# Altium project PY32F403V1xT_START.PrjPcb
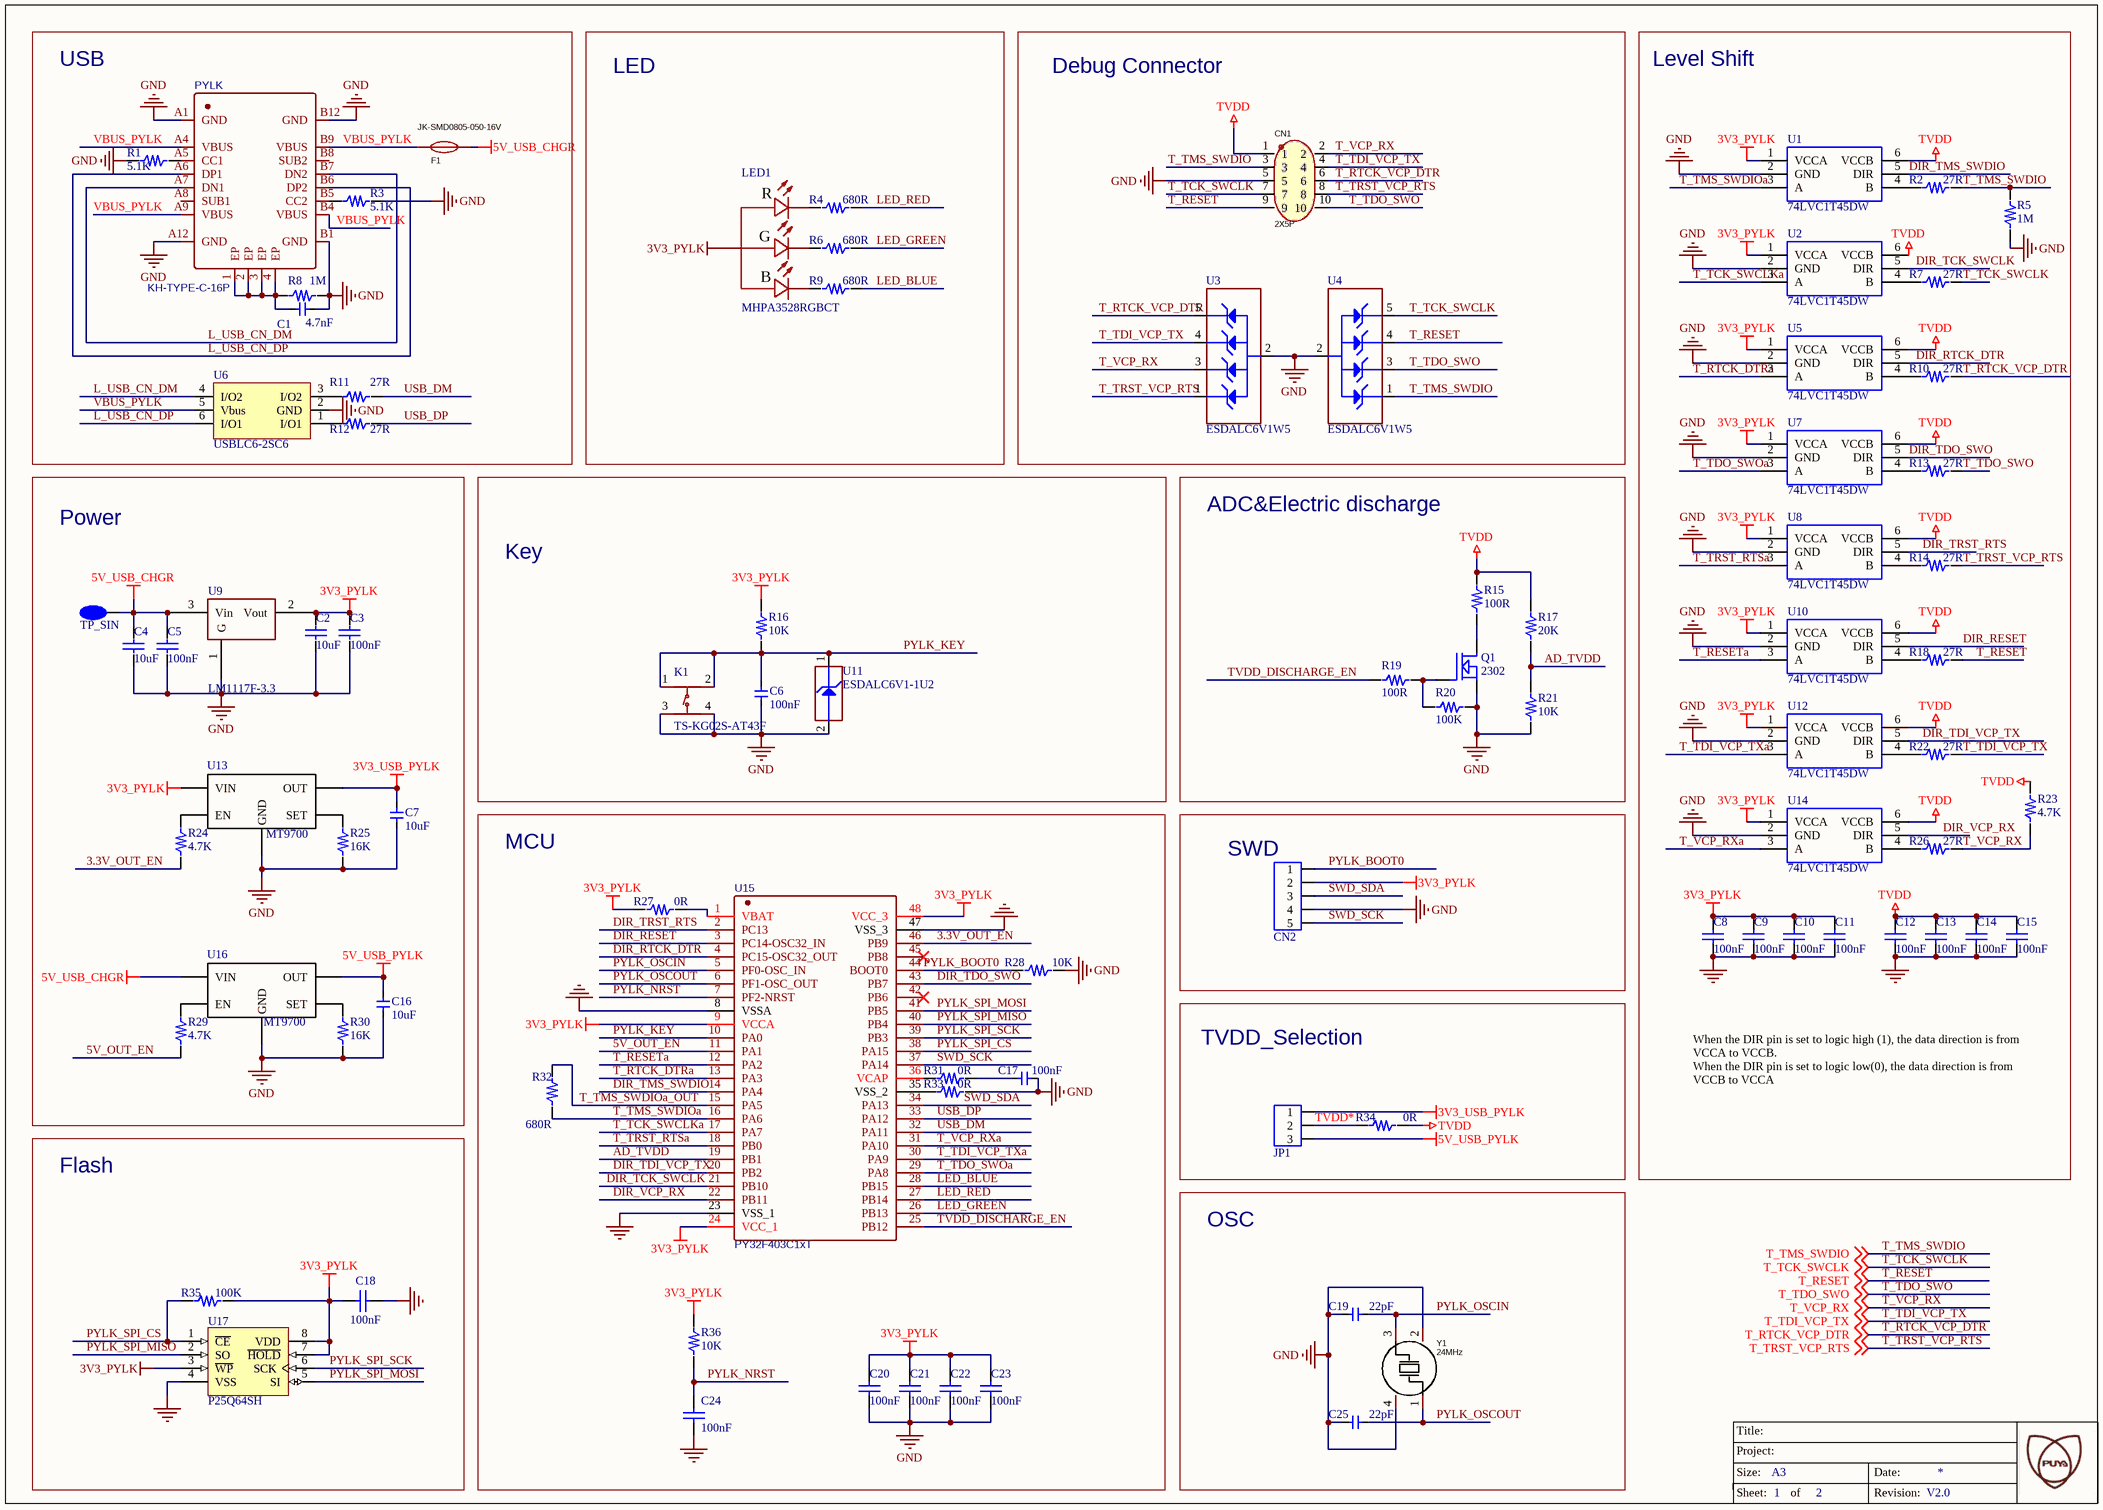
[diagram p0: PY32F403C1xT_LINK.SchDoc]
2 sheets, 171 parts. Net scope: global (net labels, ports and power ports of the same name join across sheets).
Board file: PY32F403V1xT_START.PcbDoc
Sheets:
  PY32F403C1xT_LINK.SchDoc
  PY32F403V1xT_START.SchDoc

## Sheet PY32F403C1xT_LINK.SchDoc: =DocumentName
size A3; Revision: V2.0; SheetNumber: 1; SheetTotal: 2; Project: PY32F403V1xT_START.PrjPcb

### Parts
5V_USB_CHGR  TP_SIN  [TP_SIN]
C1  4.7nF  [C0603]
C2  10uF  [C0805]
C3  100nF  [C0603]
C4  10uF  [C0805]
C5  100nF  [C0603]
C6  100nF  [C0603]
C7  10uF  [C0805]
C8  100nF  [C0603]
C9  100nF  [C0603]
C10  100nF  [C0603]
C11  100nF  [C0603]
C12  100nF  [C0603]
C13  100nF  [C0603]
C14  100nF  [C0603]
C15  100nF  [C0603]
C16  10uF  [C0805]
C17  100nF  [C0603]
C18  100nF  [C0603]
C19  22pF  [C0603]
C20  100nF  [C0603]
C21  100nF  [C0603]
C22  100nF  [C0603]
C23  100nF  [C0603]
C24  100nF  [C0603]
C25  22pF  [C0603]
CN1  2X5P  [HDR2X5]
CN2  CON5  [CON5]  (value not drawn)
F1  JK-SMD0805-050-16V  [F0805]
JP1  CON3  [CON3]  (value not drawn)
K1  TS-KG02S-AT43F  [SW-SMD_4P-L6.0-W6.0-P4.50-LS8.5]
LED1  MHPA3528RGBCT  [LED-ARRAY-SMD_4P-L3.5-W2.8-TL]
PYLK  KH-TYPE-C-16P  [USB-C-SMD_KH-TYPE-C-16P]
Q1  2302  [SOT23]
R1  5.1K  [R0603]
R2  27R  [R0603]
R3  5.1K  [R0603]
R4  680R  [R0603]
R5  1M  [R0603]
R6  680R  [R0603]
R7  27R  [R0603]
R8  1M  [R0603]
R9  680R  [R0603]
R10  27R  [R0603]
R11  27R  [R0603]
R12  27R  [R0603]
R13  27R  [R0603]
R14  27R  [R0603]
R15  100R  [R0805]
R16  10K  [R0603]
R17  20K  [R0603]
R18  27R  [R0603]
R19  100R  [R0603]
R20  100K  [R0603]
R21  10K  [R0603]
R22  27R  [R0603]
R23  4.7K  [R0603]
R24  4.7K  [R0603]
R25  16K  [R0603]
R26  27R  [R0603]
R27  0R  [JP2_SMD]
R28  10K  [R0603]
R29  4.7K  [R0603]
R30  16K  [R0603]
R31  0R  [JP2_SMD]
R32  680R  [R0603]
R33  0R  [JP2_SMD]
R34  0R  [JP2_SMD]
R35  100K  [R0603]
R36  10K  [R0603]
U1  74LVC1T45DW  [SOT363]
U2  74LVC1T45DW  [SOT363]
U3  value ESDALC6V1W5  [ESD_SOT323-5L]  (hidden comment: ESD_6V1)
U4  value ESDALC6V1W5  [ESD_SOT323-5L]  (hidden comment: ESD_6V1)
U5  74LVC1T45DW  [SOT363]
U6  USBLC6-2SC6  [SOT23-6]
U7  74LVC1T45DW  [SOT363]
U8  74LVC1T45DW  [SOT363]
U9  LM1117F-3.3  [SOT-89-3_L4.5-W2.5-P1.50-LS4.2-BR]
U10  74LVC1T45DW  [SOT363]
U11  ESDALC6V1-1U2  [ESD_ST0201]
U12  74LVC1T45DW  [SOT363]
U13  MT9700  [SOT23-5]
U14  74LVC1T45DW  [SOT363]
U15  PY32F403C1xT  [LQFP-48_L7.0-W7.0-P0.50-LS9.0-BL]
U16  MT9700  [SOT23-5]
U17  P25Q64SH  [SOP-8P]
Y1  24MHz  [CRYSTAL-SMD_4P-L3.2-W2.5-BL]

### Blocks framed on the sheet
USB: C1 F1 PYLK R1 R3 R8 R11 R12 U6
LED: LED1 R4 R6 R9
Debug Connector: CN1 U3 U4
Level Shift: C8-C15 R2 R5 R7 R10 R13 R14 R18 R22 R23 R26 U1 U2 U5 U7 U8 U10 U12 U14
Power: 5V_USB_CHGR C2-C5 C7 C16 R24 R25 R29 R30 U9 U13 U16
Key: C6 K1 R16 U11
ADC&Electric discharge: Q1 R15 R17 R19-R21
MCU: C17 C20-C24 R27 R28 R31-R33 R36 U15
SWD: CN2
TVDD_Selection: JP1 R34
Flash: C18 R35 U17
OSC: C19 C25 Y1

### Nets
3V3_PYLK: C2.2 C3.2 C8.2 C9.2 C10.2 C11.2 C18.2 C20.2 C21.2 C22.2 C23.2 CN2.2 LED1.1(-) R16.2 R27.1 R35.2 R36.2 U1.1(VCCA) U2.1(VCCA) U5.1(VCCA) U7.1(VCCA) U8.1(VCCA) U9.2(Vout) U10.1(VCCA) U12.1(VCCA) U13.5(VIN) U14.1(VCCA) U15.9(VCCA) U15.24(VCC_1) U15.48(VCC_3) U17.3(~{WP}) U17.7(~{HOLD}) U17.8(VDD)
3V3_USB_PYLK: C7.2 JP1.1 U13.1(OUT)
5V_USB_CHGR: 5V_USB_CHGR.1(TP_SIN) C4.2 C5.2 F1.2 U9.3(Vin) U16.5(VIN)
5V_USB_PYLK: C16.2 JP1.3 U16.1(OUT)
GND: C1.1 C2.1 C3.1 C4.1 C5.1 C6.1 C7.1 C8.1 C9.1 C10.1 C11.1 C12.1 C13.1 C14.1 C15.1 C16.1 C17.1 C18.1 C19.1 C20.1 C21.1 C22.1 C23.1 C24.1 C25.1 CN1.5 CN2.4 K1.3 K1.4 PYLK.A1(GND) PYLK.A12(GND) PYLK.B1(GND) PYLK.B12(GND) Q1.2(S) R1.1 R3.2 R5.1 R8.2 R20.1 R21.1 R25.1 R28.2 R30.1 R33.2 U1.2(GND) U2.2(GND) U3.2(GND) U4.2(GND) U5.2(GND) U6.2(GND) U7.2(GND) U8.2(GND) U9.1(G) U10.2(GND) U11.2(GND) U12.2(GND) U13.2(GND) U14.2(GND) U15.8(VSSA) U15.23(VSS_1) U15.47(VSS_3) U16.2(GND) U17.4(VSS) Y1.2(GND) Y1.4(GND)
TVDD: C12.2 C13.2 C14.2 C15.2 CN1.1 R15.2 R17.2 R23.2 R34.2 U1.6(VCCB) U2.6(VCCB) U5.6(VCCB) U7.6(VCCB) U8.6(VCCB) U10.6(VCCB) U12.6(VCCB) U14.6(VCCB)
3.3V_OUT_EN: R24.1 U15.46(PB9)
5V_OUT_EN: R29.1 U15.11(PA1)
AD_TVDD: R17.1 R21.2 U15.19(PB1)
DIR_RESET: U10.5(DIR) U15.3(PC14-OSC32_IN)
DIR_RTCK_DTR: U5.5(DIR) U15.4(PC15-OSC32_OUT)
DIR_TCK_SWCLK: U2.5(DIR) U15.21(PB10)
DIR_TDI_VCP_TX: U12.5(DIR) U15.20(PB2)
DIR_TDO_SWO: U7.5(DIR) U15.43(PB7)
DIR_TMS_SWDIO: U1.5(DIR) U15.14(PA4)
DIR_TRST_RTS: U8.5(DIR) U15.2(PC13)
DIR_VCP_RX: U14.5(DIR) U15.22(PB11)
L_USB_CN_DM: PYLK.A7(DN1) PYLK.B7(DN2) U6.4(I/O2)
L_USB_CN_DP: PYLK.A6(DP1) PYLK.B6(DP2) U6.6(I/O1)
LED_BLUE: R9.2 U15.28(PB15)
LED_GREEN: R6.2 U15.26(PB13)
LED_RED: R4.2 U15.27(PB14)
PYLK_BOOT0: CN2.1 R28.1 U15.44(BOOT0)
PYLK_KEY: C6.2 K1.1 K1.2 R16.1 U11.1(IO1) U15.10(PA0)
PYLK_NRST: C24.2 R36.1 U15.7(PF2-NRST)
PYLK_OSCIN: C19.2 U15.5(PF0-OSC_IN) Y1.3(OSC2)
PYLK_OSCOUT: C25.2 U15.6(PF1-OSC_OUT) Y1.1(OSC1)
PYLK_SPI_CS: R35.1 U15.38(PA15) U17.1(~{CE})
PYLK_SPI_MISO: U15.40(PB4) U17.2(SO)
PYLK_SPI_MOSI: U15.41(PB5) U17.5(SI)
PYLK_SPI_SCK: U15.39(PB3) U17.6(SCK)
SWD_SCK: CN2.5 U15.37(PA14)
SWD_SDA: CN2.3 U15.34(PA13)
T_RESET: CN1.9 R18.2 U4.4(IO3) ; off-sheet T_RESET
T_RESETa: U10.3(A) U15.12(PA2)
T_RTCK_DTRa: U5.3(A) U15.13(PA3)
T_RTCK_VCP_DTR: CN1.6 R10.2 U3.5(IO4) ; off-sheet T_RTCK_VCP_DTR
T_TCK_SWCLK: CN1.7 R7.2 U4.5(IO4) ; off-sheet T_TCK_SWCLK
T_TCK_SWCLKa: U2.3(A) U15.17(PA7)
T_TDI_VCP_TX: CN1.4 R22.2 U3.4(IO3) ; off-sheet T_TDI_VCP_TX
T_TDI_VCP_TXa: U12.3(A) U15.30(PA9)
T_TDO_SWO: CN1.10 R13.2 U4.3(IO2) ; off-sheet T_TDO_SWO
T_TDO_SWOa: U7.3(A) U15.29(PA8)
T_TMS_SWDIO: CN1.3 R2.2 R5.2 U4.1(IO1) ; off-sheet T_TMS_SWDIO
T_TMS_SWDIOa: R32.1 U1.3(A) U15.16(PA6)
T_TMS_SWDIOa_OUT: R32.2 U15.15(PA5)
T_TRST_RTSa: U8.3(A) U15.18(PB0)
T_TRST_VCP_RTS: CN1.8 R14.2 U3.1(IO1) ; off-sheet T_TRST_VCP_RTS
T_VCP_RX: CN1.2 R23.1 R26.2 U3.3(IO2) ; off-sheet T_VCP_RX
T_VCP_RXa: U14.3(A) U15.31(PA10)
TVDD*: JP1.2 R34.1
TVDD_DISCHARGE_EN: R19.2 U15.25(PB12)
USB_DM: R11.2 U15.32(PA11)
USB_DP: R12.2 U15.33(PA12)
VBUS_PYLK: F1.1 PYLK.A4(VBUS) PYLK.A9(VBUS) PYLK.B4(VBUS) PYLK.B9(VBUS) U6.5(Vbus)
NetC1_2: C1.2 PYLK.1(EP) PYLK.2(EP) PYLK.3(EP) PYLK.4(EP) R8.1
NetC17_2: C17.2 R31.2
NetLED1_2: LED1.2(-) R9.1
NetLED1_3: LED1.3(-) R6.1
NetLED1_4: LED1.4(-) R4.1
NetPYLK_A5: PYLK.A5(CC1) R1.2
NetPYLK_B5: PYLK.B5(CC2) R3.1
NetQ1_1: Q1.1(G) R19.1 R20.2
NetQ1_3: Q1.3(D) R15.1
NetR2_1: R2.1 U1.4(B)
NetR7_1: R7.1 U2.4(B)
NetR10_1: R10.1 U5.4(B)
NetR11_1: R11.1 U6.3(I/O2)
NetR12_1: R12.1 U6.1(I/O1)
NetR13_1: R13.1 U7.4(B)
NetR14_1: R14.1 U8.4(B)
NetR18_1: R18.1 U10.4(B)
NetR22_1: R22.1 U12.4(B)
NetR24_2: R24.2 U13.4(EN)
NetR25_2: R25.2 U13.3(SET)
NetR26_1: R26.1 U14.4(B)
NetR27_2: R27.2 U15.1(VBAT)
NetR29_2: R29.2 U16.4(EN)
NetR30_2: R30.2 U16.3(SET)
NetR31_1: R31.1 U15.36(VCAP)
NetR33_1: R33.1 U15.35(VSS_2)

Not connected (* = marked no-connect by the designer): PYLK A8(SUB1) B8(SUB2); U15 42(PB6)* 45(PB8)*

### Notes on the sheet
- When the DIR pin is set to logic high (1), the data direction is from VCCA to VCCB.
  When the DIR pin is set to logic low(0), the data direction is from VCCB to VCCA

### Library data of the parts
C1 C3 C5 C6 C17 C19 C25 = C0603: PCB DECAL: 0603
C2 C4 C7 C16 = C0805: PCB DECAL: 0805
C8-C15 C18 C20-C24 = 贴片高压陶瓷电容: Capacitor (Semiconductor SIM Model); 器件封装(外观): 0603; Value: 104
CN1 = 2X5P: Manufacturer: XFCN(兴飞); Symbol: PZ254V-12-10P; Add into BOM: yes; Pitch: 2.54mm; Circluar Pins/Square Pins: 方针
F1 = JK-SMD0805-050-16V: Manufacturer: JK(金科); Add into BOM: yes; Voltage - Max: 6V; Current - Max: 100A; Hold Current: 500mA; Trip Current: 1A; Power Dissipation: 600mW; Resistance - Initial (Ri) (Min): 150mΩ; Resistance - Post Trip (R1) (Max): 850mΩ; Time to Trip(Max): 100ms
K1 = TS-KG02S-AT43F: Manufacturer: HANBO(汉博); Add into BOM: yes; Circuit: 单刀单掷; Actuator Style: 圆形按钮; Operating Force: 250gf; Switch Length: 6mm; Switch Height: 4.3mm; Strike Gundam: 不带; Contact Current: 50mA; Voltage Rating (DC): 12V; Insulation Resistance: 100MΩ; Actuator/Cap Color: 黑色; Pin Style: 鸥翼型
LED1 = MHPA3528RGBCT: Manufacturer: MEIHUA(美华); Add into BOM: yes
PYLK = KH-TYPE-C-16P: BOM_Manufacturer: Shenzhen Kinghelm Elec; Contributor: LCSC
Q1 = MOSFET N: Value: SI2302
R1-R14 R16-R24 R26-R29 R31-R36 = R0603: PCB DECAL: 0603
R15 = R0805: PCB DECAL: 0805
R25 R30 = R0603_7: 0603WAF1602T5E 16KΩ(1602) ±1%; PCB DECAL: 0603
U3 U4 = ESDALC6V1W5: Dual Transil array for ESD protection; Internal_Part_Number: MCD-00136; Part_Type: Diode; Manufacturer: STMICROELECTRONICS; ECCN_US: EAR99; ECCN_EU: NEC; Provided_By: Subcon; Initial_Board_Reference: MB1262
U6 = USBLC6-2SC6: Function: ESD EMI fliter
U11 = ESDALC6V1-1U2: ESD protection 6V1; Internal_Part_Number: MCD-00170; Part_Type: Diode; Manufacturer: STMICROELECTRONICS; ECCN_US: EAR99; ECCN_EU: NEC; Provided_By: Subcon; Initial_Board_Reference: MB1274
U15 = PY32F403C1xT: LQFP48; BOM_Manufacturer: PUYA(普冉)
U17 = SST25VF010: Value: SST25VF020B; 器件封装(外观): SOP8
Y1 = ABM8AIG-24.000MHZ-82Z-T: ±20ppm , 12.5pF , T_use: -40°C~125°C; Manufacturer: ABRACON; Add into BOM: yes; External load capacitor: 8pF; Frequency Stability(Full temperature range): ±50ppm; Equivalent Series Resistance (ESR): 50Ω

## Sheet PY32F403V1xT_START.SchDoc: =DocumentName
size A3; Revision: V2.0; SheetNumber: 2; SheetTotal: 2; Project: PY32F403V1xT_START.PrjPcb
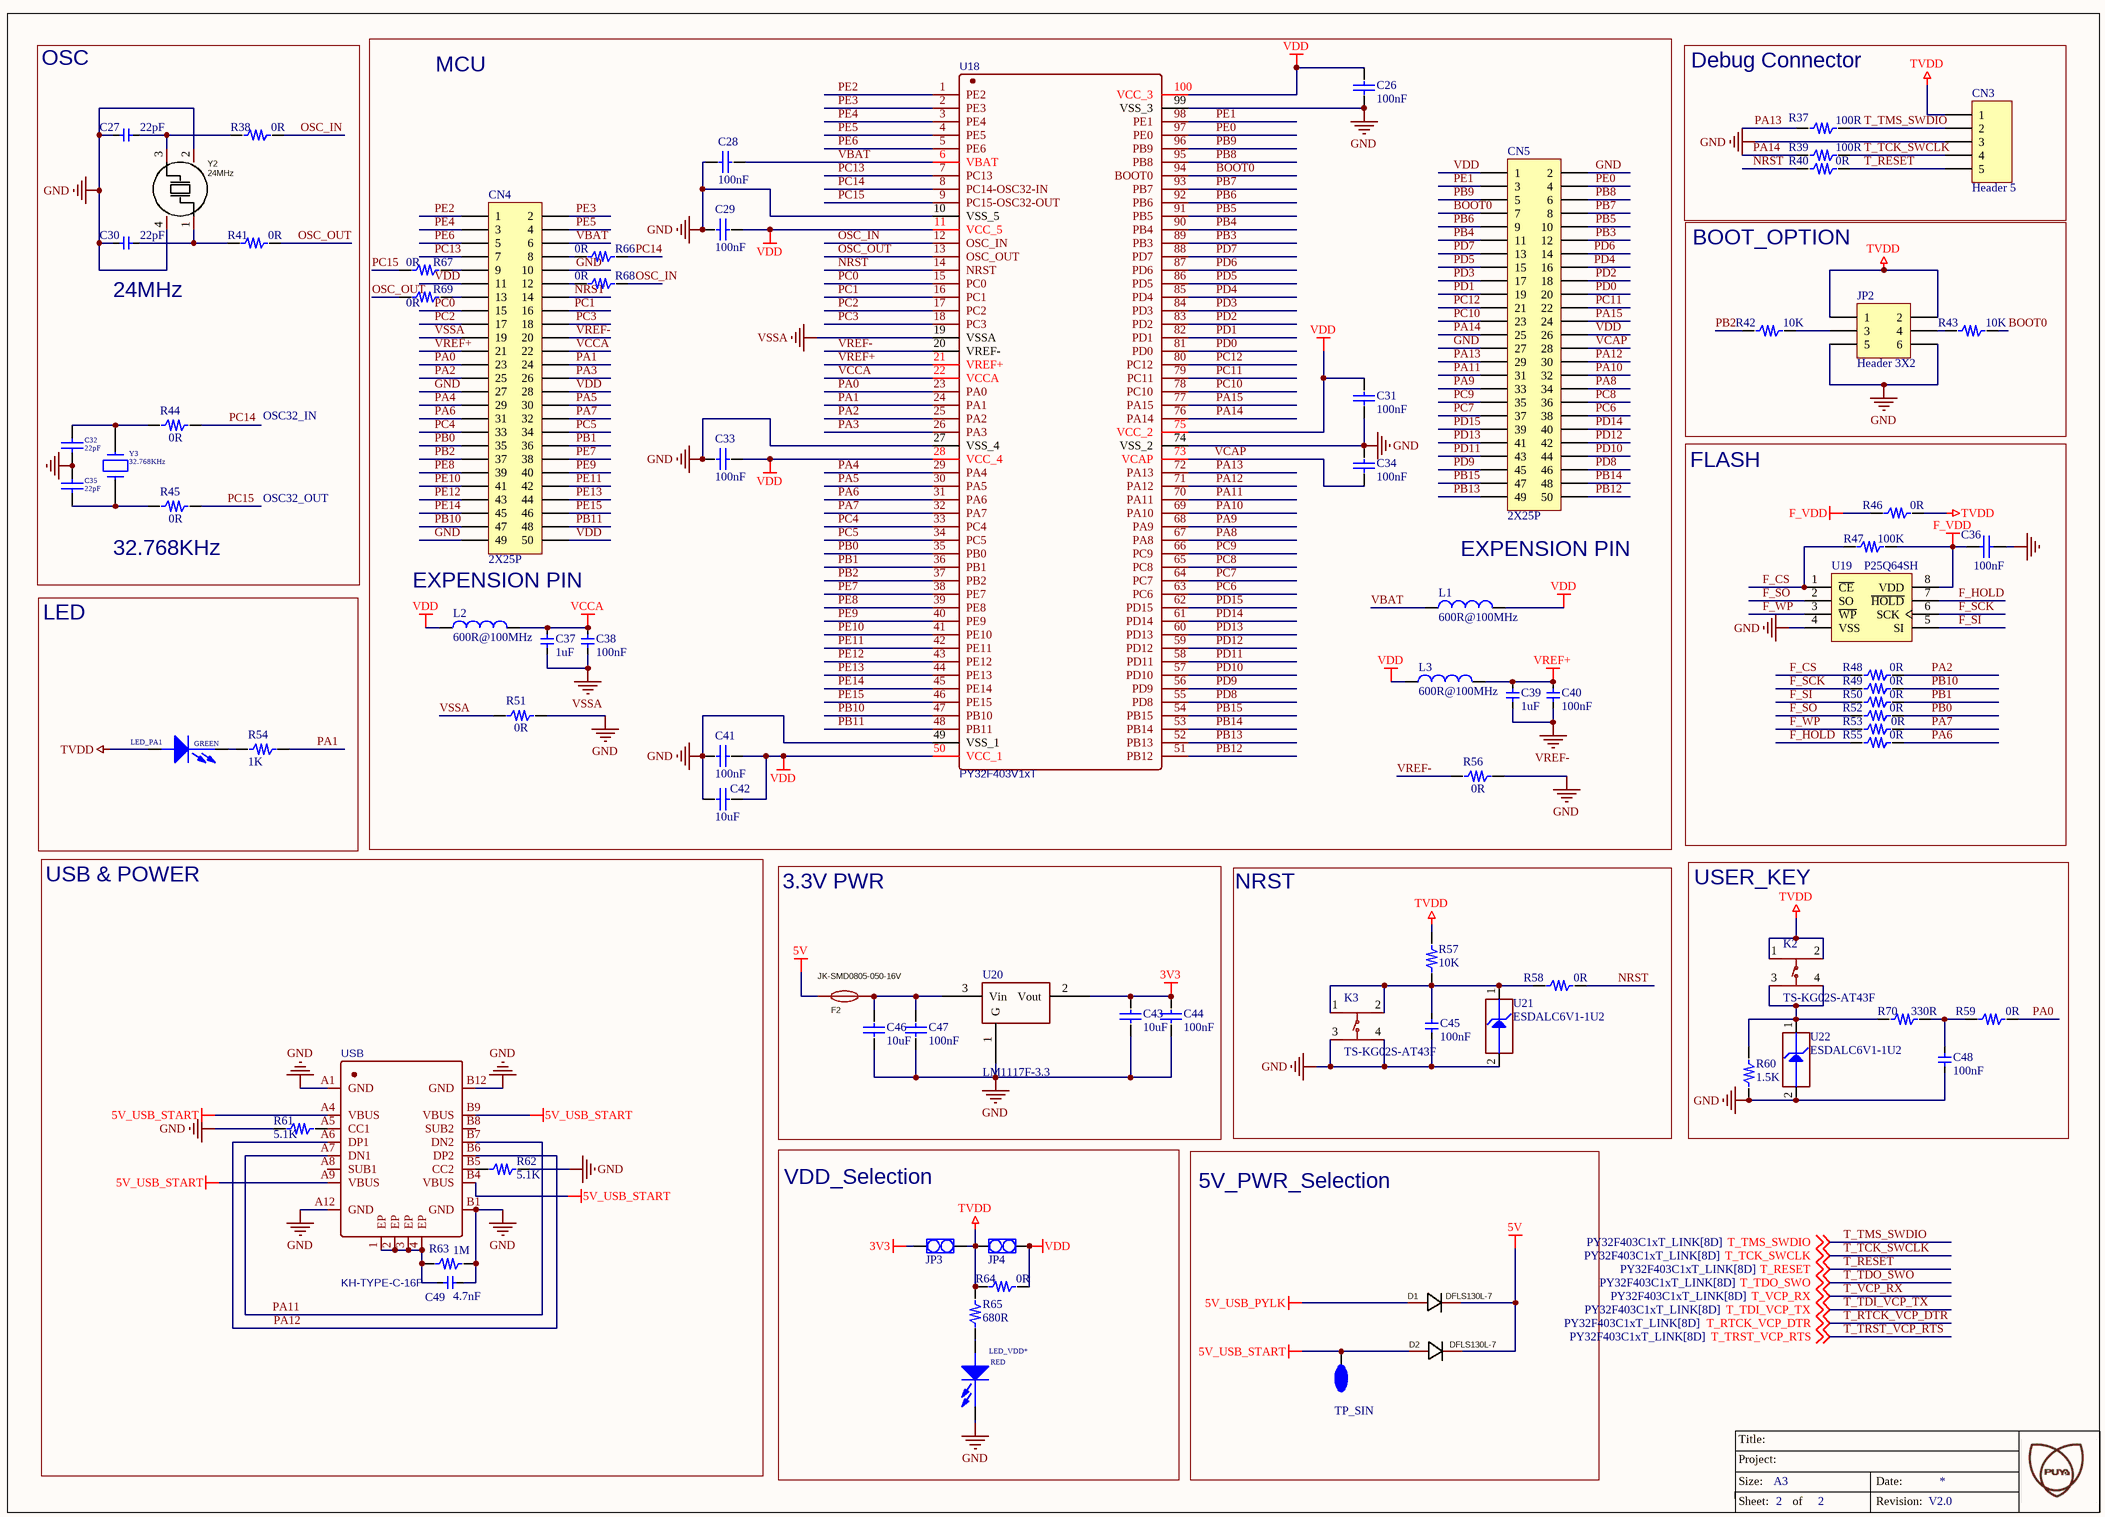
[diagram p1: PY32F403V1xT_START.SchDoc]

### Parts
5V_USB_START  TP_SIN  [TP_SIN]
C26  100nF  [c0603cap]
C27  22pF  [C0603]
C28  100nF  [c0603cap]
C29  100nF  [c0603cap]
C30  22pF  [C0603]
C31  100nF  [c0603cap]
C32  22pF  [C0603]
C33  100nF  [c0603cap]
C34  100nF  [c0603cap]
C35  22pF  [C0603]
C36  100nF  [C0603]
C37  1uF  [C0603]
C38  100nF  [C0603]
C39  1uF  [C0603]
C40  100nF  [C0603]
C41  100nF  [c0603cap]
C42  10uF  [c0603cap]
C43  10uF  [C0805]
C44  100nF  [C0603]
C45  100nF  [C0603]
C46  10uF  [C0805]
C47  100nF  [C0603]
C48  100nF  [C0603]
C49  4.7nF  [C0603]
CN3  Header 5  [HDR1X5]
CN4  2X25P  [HDR2X25]
CN5  2X25P  [HDR2X25]
D1  DFLS130L-7  [POWERDI-123_L2.8-W1.8-LS3.7-RD]
D2  DFLS130L-7  [POWERDI-123_L2.8-W1.8-LS3.7-RD]
F2  JK-SMD0805-050-16V  [F0805]
JP2  Header 3X2  [HDR2X3]
JP3  CON2  [CON2]  (value not drawn)
JP4  CON2  [CON2]  (value not drawn)
K2  TS-KG02S-AT43F  [SW-SMD_4P-L6.0-W6.0-P4.50-LS8.5]
K3  TS-KG02S-AT43F  [SW-SMD_4P-L6.0-W6.0-P4.50-LS8.5]
L1  value 600R@100MHz  [L0603]  (hidden comment: GZ1608D601TF)
L2  value 600R@100MHz  [L0603]  (hidden comment: GZ1608D601TF)
L3  value 600R@100MHz  [L0603]  (hidden comment: GZ1608D601TF)
LED_PA1  GREEN  [0603_LED]
LED_VDD*  RED  [0603_LED]
R37  100R  [R0603]
R38  0R  [JP2_SMD]
R39  100R  [R0603]
R40  0R  [R0603]
R41  0R  [JP2_SMD]
R42  10K  [R0603]
R43  10K  [R0603]
R44  0R  [JP2_SMD]
R45  0R  [JP2_SMD]
R46  0R  [JP2_SMD]
R47  100K  [R0603]
R48  0R  [R0603]
R49  0R  [R0603]
R50  0R  [R0603]
R51  0R  [JP2_SMD]
R52  0R  [R0603]
R53  0R  [R0603]
R54  1K  [R0603]
R55  0R  [R0603]
R56  0R  [JP2_SMD]
R57  10K  [R0603]
R58  0R  [JP2_SMD]
R59  0R  [JP2_SMD]
R60  1.5K  [R0603]
R61  5.1K  [R0603]
R62  5.1K  [R0603]
R63  1M  [R0603]
R64  0R  [JP2_SMD]
R65  680R  [R0603]
R66  0R  [JP2_SMD]
R67  0R  [JP2_SMD]
R68  0R  [JP2_SMD]
R69  0R  [JP2_SMD]
R70  330R  [R0603]
U18  PY32F403V1xT  [LQFP-100_L14.0-W14.0-P0.50-LS16.0-BL]
U19  P25Q64SH  [SOP-8P]
U20  LM1117F-3.3  [SOT-89-3_L4.5-W2.5-P1.50-LS4.2-BR]
U21  ESDALC6V1-1U2  [ESD_ST0201]
U22  ESDALC6V1-1U2  [ESD_ST0201]
USB  KH-TYPE-C-16P  [USB-C-SMD_KH-TYPE-C-16P]
Y2  24MHz  [CRYSTAL-SMD_4P-L3.2-W2.5-BL]
Y3  32.768KHz  [CRYSTAL-SMD_L3.2-W1.5-1]

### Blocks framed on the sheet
Debug Connector: CN3 R37 R39 R40
BOOT_OPTION: JP2 R42 R43
FLASH: C36 R46-R50 R52 R53 R55 U19
LED: LED_PA1 R54
USB & POWER: C49 R61-R63 USB
3.3V PWR: C43 C44 C46 C47 F2 U20
NRST: C45 K3 R57 R58 U21
USER_KEY: C48 K2 R59 R60 R70 U22
VDD_Selection: JP3 JP4 LED_VDD* R64 R65
5V_PWR_Selection: 5V_USB_START D1 D2

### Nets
3V3: C43.2 C44.2 JP3.2 U20.2(Vout)
5V: D1.1 D2.1 F2.1
5V_USB_PYLK: D1.2
5V_USB_START: 5V_USB_START.1(TP_SIN) D2.2 USB.A4(VBUS) USB.A9(VBUS) USB.B4(VBUS) USB.B9(VBUS)
F_VDD: C36.2 R46.2 R47.2 U19.8(VDD)
GND: C26.1 C27.1 C28.1 C29.1 C30.1 C31.2 C32.2 C33.2 C34.2 C35.1 C36.1 C41.1 C42.1 C43.1 C44.1 C45.1 C46.1 C47.1 C48.1 C49.1 CN3.3 CN4.10 CN4.27 CN4.49 CN5.2 CN5.27 JP2.5 JP2.6 K3.3 K3.4 LED_VDD*.2(CATHODE) R51.1 R56.1 R60.1 R61.2 R62.1 R63.1 U18.10(VSS_5) U18.27(VSS_4) U18.49(VSS_1) U18.74(VSS_2) U18.99(VSS_3) U19.4(VSS) U20.1(G) U21.2(GND) U22.2(GND) USB.A1(GND) USB.A12(GND) USB.B1(GND) USB.B12(GND) Y2.2(GND) Y2.4(GND)
TVDD: CN3.1 JP2.1 JP2.2 JP3.1 JP4.1 K2.1 K2.2 LED_PA1.1(ANODE) R46.1 R57.1 R64.1 R65.2
VCCA: C37.2 C38.2 CN4.22 L2.2 U18.22(VCCA)
VDD: C26.2 C29.2 C31.1 C33.1 C41.2 C42.2 CN4.11 CN4.28 CN4.50 CN5.1 CN5.26 JP4.2 L1.2 L2.1 L3.1 R64.2 U18.11(VCC_5) U18.28(VCC_4) U18.50(VCC_1) U18.75(VCC_2) U18.100(VCC_3)
VREF+: C39.2 C40.2 CN4.21 L3.2 U18.21(VREF+)
VREF-: C39.1 C40.1 CN4.20 R56.2 U18.20(VREF-)
VSSA: C37.1 C38.1 CN4.19 R51.2 U18.19(VSSA)
BOOT0: CN5.7 R43.2 U18.94(BOOT0)
F_CS: R47.1 R48.2 U19.1(~{CE})
F_HOLD: R55.2 U19.7(~{HOLD})
F_SCK: R49.2 U19.6(SCK)
F_SI: R50.2 U19.5(SI)
F_SO: R52.2 U19.2(SO)
F_WP: R53.2 U19.3(~{WP})
NRST: CN4.14 R40.2 R58.2 U18.14(NRST)
OSC_IN: R38.2 R68.2 U18.12(OSC_IN)
OSC_OUT: R41.2 R69.2 U18.13(OSC_OUT)
PA0: CN4.23 R59.2 U18.23(PA0)
PA1: CN4.24 R54.2 U18.24(PA1)
PA2: CN4.25 R48.1 U18.25(PA2)
PA3: CN4.26 U18.26(PA3)
PA4: CN4.29 U18.29(PA4)
PA5: CN4.30 U18.30(PA5)
PA6: CN4.31 R55.1 U18.31(PA6)
PA7: CN4.32 R53.1 U18.32(PA7)
PA8: CN5.34 U18.67(PA8)
PA9: CN5.33 U18.68(PA9)
PA10: CN5.32 U18.69(PA10)
PA11: CN5.31 U18.70(PA11) USB.A7(DN1) USB.B7(DN2)
PA12: CN5.30 U18.71(PA12) USB.A6(DP1) USB.B6(DP2)
PA13: CN5.29 R37.2 U18.72(PA13)
PA14: CN5.25 R39.2 U18.76(PA14)
PA15: CN5.24 U18.77(PA15)
PB0: CN4.35 R52.1 U18.35(PB0)
PB1: CN4.36 R50.1 U18.36(PB1)
PB2: CN4.37 R42.1 U18.37(PB2)
PB3: CN5.12 U18.89(PB3)
PB4: CN5.11 U18.90(PB4)
PB5: CN5.10 U18.91(PB5)
PB6: CN5.9 U18.92(PB6)
PB7: CN5.8 U18.93(PB7)
PB8: CN5.6 U18.95(PB8)
PB9: CN5.5 U18.96(PB9)
PB10: CN4.47 R49.1 U18.47(PB10)
PB11: CN4.48 U18.48(PB11)
PB12: CN5.50 U18.51(PB12)
PB13: CN5.49 U18.52(PB13)
PB14: CN5.48 U18.53(PB14)
PB15: CN5.47 U18.54(PB15)
PC0: CN4.15 U18.15(PC0)
PC1: CN4.16 U18.16(PC1)
PC2: CN4.17 U18.17(PC2)
PC3: CN4.18 U18.18(PC3)
PC4: CN4.33 U18.33(PC4)
PC5: CN4.34 U18.34(PC5)
PC6: CN5.38 U18.63(PC6)
PC7: CN5.37 U18.64(PC7)
PC8: CN5.36 U18.65(PC8)
PC9: CN5.35 U18.66(PC9)
PC10: CN5.23 U18.78(PC10)
PC11: CN5.22 U18.79(PC11)
PC12: CN5.21 U18.80(PC12)
PC13: CN4.7 U18.7(PC13)
PC14: R44.1 R66.1 U18.8(PC14-OSC32-IN)
PC15: R45.1 R67.1 U18.9(PC15-OSC32-OUT)
PD0: CN5.20 U18.81(PD0)
PD1: CN5.19 U18.82(PD1)
PD2: CN5.18 U18.83(PD2)
PD3: CN5.17 U18.84(PD3)
PD4: CN5.16 U18.85(PD4)
PD5: CN5.15 U18.86(PD5)
PD6: CN5.14 U18.87(PD6)
PD7: CN5.13 U18.88(PD7)
PD8: CN5.46 U18.55(PD8)
PD9: CN5.45 U18.56(PD9)
PD10: CN5.44 U18.57(PD10)
PD11: CN5.43 U18.58(PD11)
PD12: CN5.42 U18.59(PD12)
PD13: CN5.41 U18.60(PD13)
PD14: CN5.40 U18.61(PD14)
PD15: CN5.39 U18.62(PD15)
PE0: CN5.4 U18.97(PE0)
PE1: CN5.3 U18.98(PE1)
PE2: CN4.1 U18.1(PE2)
PE3: CN4.2 U18.2(PE3)
PE4: CN4.3 U18.3(PE4)
PE5: CN4.4 U18.4(PE5)
PE6: CN4.5 U18.5(PE6)
PE7: CN4.38 U18.38(PE7)
PE8: CN4.39 U18.39(PE8)
PE9: CN4.40 U18.40(PE9)
PE10: CN4.41 U18.41(PE10)
PE11: CN4.42 U18.42(PE11)
PE12: CN4.43 U18.43(PE12)
PE13: CN4.44 U18.44(PE13)
PE14: CN4.45 U18.45(PE14)
PE15: CN4.46 U18.46(PE15)
T_RESET: CN3.5 R40.1 ; off-sheet T_RESET
T_TCK_SWCLK: CN3.4 R39.1 ; off-sheet T_TCK_SWCLK
T_TMS_SWDIO: CN3.2 R37.1 ; off-sheet T_TMS_SWDIO
VBAT: C28.2 CN4.6 L1.1 U18.6(VBAT)
VCAP: C34.1 CN5.28 U18.73(VCAP)
NetC27_2: C27.2 R38.1 Y2.3(OSC2)
NetC30_2: C30.2 R41.1 Y2.1(OSC1)
NetC32_1: C32.1 R44.2 Y3.1
NetC35_2: C35.2 R45.2 Y3.2
NetC45_2: C45.2 K3.1 K3.2 R57.2 R58.1 U21.1(IO1)
NetC46_2: C46.2 C47.2 F2.2 U20.3(Vin)
NetC48_2: C48.2 R59.1 R70.1
NetC49_2: C49.2 R63.2 USB.1(EP) USB.2(EP) USB.3(EP) USB.4(EP)
NetCN4_8: CN4.8 R66.2
NetCN4_9: CN4.9 R67.2
NetCN4_12: CN4.12 R68.1
NetCN4_13: CN4.13 R69.1
NetJP2_3: JP2.3 R42.2
NetJP2_4: JP2.4 R43.1
NetK2_3: K2.3 K2.4 R60.2 R70.2 U22.1(IO1)
NetLED_PA1_2: LED_PA1.2(CATHODE) R54.1
NetLED_VDD*_1: LED_VDD*.1(ANODE) R65.1
NetR61_1: R61.1 USB.A5(CC1)
NetR62_2: R62.2 USB.B5(CC2)

Not connected (* = marked no-connect by the designer): USB A8(SUB1) B8(SUB2)

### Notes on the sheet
- OSC
- MCU
- (near C30) 24MHz
- OSC32_IN
- OSC32_OUT
- (near R45) 32.768KHz
- EXPENSION PIN

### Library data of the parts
C26-C31 C33 C34 C38 C40-C42 C44 C45 C47-C49 = C0603: PCB DECAL: 0603
C32 C35 = Cap: Capacitor
C36 = 贴片高压陶瓷电容: as C8 on sheet PY32F403C1xT_LINK
C37 C39 C43 C46 = C0805: PCB DECAL: 0805
CN3 = Header 5: Header, 5-Pin
CN4 CN5 = Header 25X2: Header, 25-Pin, Dual row
D1 D2 = DFLS130L-7: Manufacturer: DIODES(美台); Add into BOM: yes; Forward Voltage (Vf@If): 310mV@1A; Reverse Voltage (Vr): 30V; Average Rectified Current (Io): 1A
F2 = JK-SMD0805-050-16V: as F1 on sheet PY32F403C1xT_LINK
JP2 = Header 3X2: Header, 3-Pin, Dual row
JP3 JP4 = CON2_DIP
K2 K3 = TS-KG02S-AT43F: as K1 on sheet PY32F403C1xT_LINK
L1-L3 = GZ1608D601TF: SMD Chip ferrite bead, 600R@100MHz +/-25%, 350mA, 500mohm DC, 0603, T=0.8mm; Internal_Part_Number: MCD-00047; Part_Type: Inductor; Manufacturer_Part_Number: FCM1608KF-601T03; Manufacturer: TAI-TECH; Provided_By: SUBCO
LED_PA1 LED_VDD* = PDI-E803_Dup1
R37-R70 = R0603: PCB DECAL: 0603
U18 = PY32F403V1xT: LQFP100; BOM_Manufacturer: PUYA(普冉)
U19 = SST25VF010: Value: SST25VF020B; 器件封装(外观): SOP8
U21 U22 = ESDALC6V1-1U2: as U11 on sheet PY32F403C1xT_LINK
USB = KH-TYPE-C-16P: as PYLK on sheet PY32F403C1xT_LINK
Y2 = ABM8AIG-24.000MHZ-82Z-T: as Y1 on sheet PY32F403C1xT_LINK
Y3 = SC-32S32.768kHz20PPM12.5pF: Crystal; Value: X503225MSB2GI

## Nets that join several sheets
5V_USB_PYLK: PY32F403C1xT_LINK (C16.2 JP1.3 U16.1), PY32F403V1xT_START (D1.2)
GND: PY32F403C1xT_LINK (65 pins), PY32F403V1xT_START (52 pins)
TVDD: PY32F403C1xT_LINK (17 pins), PY32F403V1xT_START (12 pins)
T_RESET: PY32F403C1xT_LINK (CN1.9 R18.2 U4.4), PY32F403V1xT_START (CN3.5 R40.1)
T_TCK_SWCLK: PY32F403C1xT_LINK (CN1.7 R7.2 U4.5), PY32F403V1xT_START (CN3.4 R39.1)
T_TMS_SWDIO: PY32F403C1xT_LINK (CN1.3 R2.2 R5.2 U4.1), PY32F403V1xT_START (CN3.2 R37.1)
